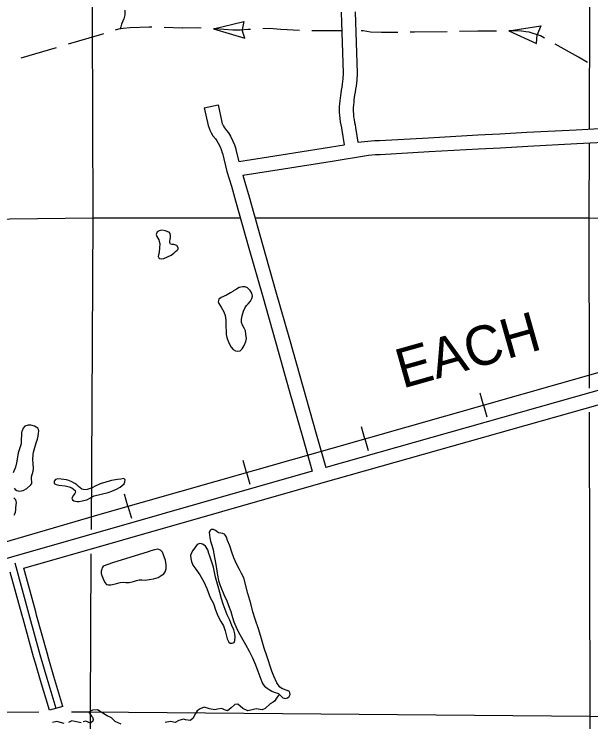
# Model space of a CAD drawing. Extents: x 1373094 to 1376427, y 1168361 to 1170494.
# Drawn here: x 1373576.1 to 1373679.1, y 1169997.1 to 1170123.5 of the extents above; entities that cross this region are included whole.
import ezdxf

# ---------------------------------------------------------------- set-up
doc = ezdxf.new("R2010")
doc.units = 0
doc.layers.add('R_Axis', color=7, linetype='Continuous')

msp = doc.modelspace()

# ---------------------------------------------------------------- linework, layer by layer
at = {"layer": 'R_Axis'}
for p, q in [((1373611.69, 1170120.9), (1373617.1, 1170122.17)), ((1373617.1, 1170122.17), (1373616.8, 1170120.68)), ((1373611.69, 1170120.9), (1373617.3, 1170119.22)), ((1373664.42, 1170120.5), (1373670.14, 1170121.4)), ((1373670.14, 1170121.4), (1373669.47, 1170119.82)), ((1373617.3, 1170119.22), (1373616.8, 1170120.66)), ((1373664.42, 1170120.5), (1373669.39, 1170118.28)), ((1373669.39, 1170118.28), (1373669.47, 1170119.8)), ((1373610.04, 1170106.78), (1373612.49, 1170107.32)), ((1373659.89, 1170053.66), (1373659.29, 1170055.78)), ((1373659.89, 1170053.66), (1373660.49, 1170051.54)), ((1373638.73, 1170047.64), (1373638.13, 1170049.76)), ((1373638.73, 1170047.64), (1373639.33, 1170045.53)), ((1373617.57, 1170041.63), (1373616.97, 1170043.74)), ((1373617.57, 1170041.63), (1373618.17, 1170039.51)), ((1373596.41, 1170035.61), (1373595.81, 1170037.72)), ((1373596.41, 1170035.61), (1373597.01, 1170033.49)), ((1373584.77, 1169999.84), (1373582.37, 1169999.14))]:
    msp.add_line(p, q, dxfattribs=at)
for points in [[(1373590.16, 1170175.98), (1373590.03, 1170122.63)], [(1373678.85, 1170124.81), (1373678.77, 1170102.99)], [(1373595.83, 1170124.22), (1373595.86, 1170123.4), (1373595.68, 1170122.68), (1373595.44, 1170122.13), (1373595.25, 1170121.69), (1373595.13, 1170121.25), (1373594.99, 1170120.85)], [(1373634.48, 1170123.86), (1373634.82, 1170112.94), (1373634.79, 1170111.92), (1373634.67, 1170110.98), (1373634.59, 1170110.46), (1373634.5, 1170109.94), (1373634.42, 1170109.4), (1373634.34, 1170108.94), (1373634.29, 1170108.47), (1373634.23, 1170108.02), (1373634.19, 1170107.5), (1373634.14, 1170106.99), (1373634.12, 1170106.61), (1373634.11, 1170106.01), (1373634.18, 1170105.4), (1373634.22, 1170104.84), (1373634.33, 1170104.25), (1373634.41, 1170103.71), (1373634.52, 1170103.21), (1373634.61, 1170102.78), (1373635, 1170100.13)], [(1373636.98, 1170123.92), (1373637.32, 1170112.94), (1373637.29, 1170111.72), (1373637.14, 1170110.62), (1373637.05, 1170110.07), (1373636.97, 1170109.55), (1373636.89, 1170109.01), (1373636.82, 1170108.6), (1373636.77, 1170108.17), (1373636.72, 1170107.78), (1373636.69, 1170107.29), (1373636.63, 1170106.77), (1373636.62, 1170106.51), (1373636.61, 1170106.15), (1373636.68, 1170105.62), (1373636.71, 1170105.15), (1373636.79, 1170104.67), (1373636.87, 1170104.15), (1373636.96, 1170103.72), (1373637.07, 1170103.22), (1373637.46, 1170100.62)], [(1373590.03, 1170122.63), (1373590.11, 1170087.11), (1373589.81, 1170031.44)], [(1373600.69, 1170121.16), (1373600.18, 1170121.17), (1373596.77, 1170121.08), (1373595.54, 1170120.95), (1373594.72, 1170120.81), (1373594.14, 1170120.63)], [(1373606.19, 1170121), (1373606.12, 1170121), (1373602.89, 1170121.09)], [(1373609.49, 1170121.01), (1373608.98, 1170121.04), (1373606.19, 1170121)], [(1373618.27, 1170120.77), (1373617.81, 1170120.74), (1373616.46, 1170120.65), (1373615.13, 1170120.61), (1373613.53, 1170120.74), (1373611.9, 1170120.86), (1373611.68, 1170120.87)], [(1373627.05, 1170120.55), (1373627.03, 1170120.55), (1373623.73, 1170120.75), (1373621.64, 1170120.94), (1373620.47, 1170120.89)], [(1373592.04, 1170119.96), (1373591.26, 1170119.73), (1373585.71, 1170118.11)], [(1373634.58, 1170120.5), (1373629.25, 1170120.54)], [(1373644.62, 1170120.24), (1373641.69, 1170120.19), (1373639.73, 1170120.28), (1373638.44, 1170120.51), (1373638.05, 1170120.53)], [(1373653.42, 1170120.36), (1373647.58, 1170120.29), (1373646.82, 1170120.28)], [(1373658.92, 1170120.43), (1373655.62, 1170120.39)], [(1373662.22, 1170120.47), (1373658.92, 1170120.43)], [(1373670.8, 1170119.22), (1373670.09, 1170119.62), (1373668.04, 1170120.27), (1373667.47, 1170120.32), (1373666.67, 1170120.45), (1373665.3, 1170120.51), (1373664.42, 1170120.5)], [(1373583.6, 1170117.5), (1373577.26, 1170115.65)], [(1373678.46, 1170114.87), (1373676.87, 1170115.82), (1373672.72, 1170118.14)], [(1373612.49, 1170107.32), (1373613.17, 1170104.22), (1373613.25, 1170103.93), (1373613.29, 1170103.83), (1373613.46, 1170103.5), (1373613.65, 1170103.2), (1373614.01, 1170102.71), (1373614.34, 1170102.28), (1373614.71, 1170101.69), (1373615.15, 1170100.83), (1373615.42, 1170100.14), (1373615.65, 1170099.42), (1373615.69, 1170099.28)], [(1373610.04, 1170106.78), (1373610.74, 1170103.61), (1373610.89, 1170103.11), (1373611.02, 1170102.78), (1373611.28, 1170102.27), (1373611.58, 1170101.79), (1373612.01, 1170101.21), (1373612.28, 1170100.86), (1373612.54, 1170100.45), (1373612.87, 1170099.81), (1373613.06, 1170099.31), (1373613.25, 1170098.74), (1373613.26, 1170098.67)], [(1373676.46, 1170102.86), (1373684.91, 1170103.32), (1373685.32, 1170103.32)], [(1373650.09, 1170101.43), (1373658.88, 1170101.91)], [(1373658.88, 1170101.91), (1373662.81, 1170102.13), (1373667.67, 1170102.39)], [(1373667.67, 1170102.39), (1373676.46, 1170102.86)], [(1373637.46, 1170100.62), (1373640.45, 1170100.9), (1373641.31, 1170100.95)], [(1373641.31, 1170100.95), (1373650.09, 1170101.43)], [(1373676.59, 1170100.37), (1373684.96, 1170100.82), (1373685.3, 1170100.82)], [(1373623.78, 1170098.35), (1373635, 1170100.13)], [(1373650.23, 1170098.94), (1373659.02, 1170099.42)], [(1373659.02, 1170099.42), (1373662.95, 1170099.63), (1373667.8, 1170099.9)], [(1373667.8, 1170099.9), (1373676.59, 1170100.37)], [(1373678.76, 1170100.49), (1373678.71, 1170087.1), (1373678.77, 1170056.7)], [(1373613.26, 1170098.67), (1373614.08, 1170095.4), (1373614.87, 1170092.78), (1373615.62, 1170090.15)], [(1373615.69, 1170099.28), (1373616.22, 1170097.15)], [(1373616.22, 1170097.15), (1373623.78, 1170098.35)], [(1373632.86, 1170097.26), (1373639.39, 1170098.29), (1373640.64, 1170098.41), (1373641.44, 1170098.45)], [(1373641.44, 1170098.45), (1373650.23, 1170098.94)], [(1373624.17, 1170095.88), (1373632.86, 1170097.26)], [(1373616.9, 1170094.72), (1373624.17, 1170095.88)], [(1373616.9, 1170094.72), (1373617.27, 1170093.49), (1373618.03, 1170090.84)], [(1373618.03, 1170090.84), (1373620.43, 1170082.37)], [(1373615.62, 1170090.15), (1373618.02, 1170081.69)], [(1373535.69, 1170086.46), (1373590.11, 1170087.11), (1373616.48, 1170087.11)], [(1373619.08, 1170087.11), (1373678.71, 1170087.1), (1373747.2, 1170084.66)], [(1373603.93, 1170084.29), (1373603.74, 1170084.53), (1373603.52, 1170084.63), (1373603.1, 1170084.8), (1373602.48, 1170084.89), (1373601.99, 1170084.78), (1373601.63, 1170084.6), (1373601.46, 1170084.16), (1373601.58, 1170083.78), (1373601.89, 1170083.16), (1373602.11, 1170082.43), (1373602.06, 1170081.83), (1373601.95, 1170080.94), (1373601.88, 1170080.49), (1373601.82, 1170080.23), (1373601.9, 1170079.95), (1373602.03, 1170079.86), (1373602.32, 1170079.76), (1373602.8, 1170079.86), (1373603.46, 1170080.12), (1373604.11, 1170080.47), (1373604.58, 1170080.8), (1373604.92, 1170081.08), (1373605.17, 1170081.32), (1373605.36, 1170081.53), (1373605.39, 1170081.76), (1373605.16, 1170082.19), (1373604.59, 1170082.32), (1373604.21, 1170082.33), (1373604.02, 1170082.39), (1373603.92, 1170082.5), (1373603.88, 1170082.7), (1373603.9, 1170082.97), (1373603.96, 1170083.3), (1373604, 1170083.57), (1373603.99, 1170083.91), (1373603.93, 1170084.29)], [(1373618.02, 1170081.69), (1373620.42, 1170073.22)], [(1373620.43, 1170082.37), (1373622.83, 1170073.9)], [(1373546.2, 1170020.93), (1373591.87, 1170034.32), (1373741.71, 1170076.93)], [(1373546.2, 1170020.93), (1373591.87, 1170034.32), (1373741.71, 1170076.93)], [(1373755.25, 1170077.44), (1373631.72, 1170042.54)], [(1373577.78, 1170024.53), (1373630.86, 1170039.7), (1373756.46, 1170075.18)], [(1373615.27, 1170074.05), (1373615.15, 1170073.96), (1373614.73, 1170073.73), (1373614.01, 1170073.32), (1373613.06, 1170072.88), (1373612.61, 1170072.6), (1373612.53, 1170072.13), (1373612.61, 1170071.78), (1373613.07, 1170071.14), (1373613.55, 1170070.32), (1373613.78, 1170069.66), (1373613.91, 1170068.81), (1373613.89, 1170067.71), (1373613.92, 1170066.84), (1373613.95, 1170066.28), (1373614.07, 1170065.74), (1373614.34, 1170064.89), (1373614.82, 1170064), (1373615.21, 1170063.59), (1373615.59, 1170063.37), (1373616.02, 1170063.28), (1373616.43, 1170063.36), (1373616.81, 1170063.71), (1373617.17, 1170064.3), (1373617.47, 1170065), (1373617.58, 1170065.57), (1373617.48, 1170066.33), (1373617.38, 1170066.93), (1373617.15, 1170067.41), (1373616.86, 1170067.93), (1373616.67, 1170068.43), (1373616.68, 1170069.01), (1373616.81, 1170069.6), (1373617.04, 1170070.44), (1373617.32, 1170071.09), (1373617.56, 1170071.44), (1373617.85, 1170071.77), (1373618.28, 1170072.22), (1373618.53, 1170072.69), (1373618.62, 1170073.13), (1373618.52, 1170073.66), (1373618.22, 1170074.15), (1373617.76, 1170074.61), (1373617.36, 1170074.78), (1373616.84, 1170074.81), (1373616.26, 1170074.68), (1373615.77, 1170074.39), (1373615.27, 1170074.05)], [(1373620.42, 1170073.22), (1373622.82, 1170064.76)], [(1373622.83, 1170073.9), (1373625.23, 1170065.44)], [(1373625.23, 1170065.44), (1373627.63, 1170056.97)], [(1373622.82, 1170064.76), (1373625.22, 1170056.29)], [(1373627.63, 1170056.97), (1373630.03, 1170048.5)], [(1373625.22, 1170056.29), (1373627.62, 1170047.82)], [(1373678.78, 1170052.37), (1373678.87, 1169998.09), (1373678.78, 1169973.84)], [(1373580.32, 1170049.55), (1373579.71, 1170049.89), (1373579.06, 1170050.06), (1373578.59, 1170050.09), (1373578, 1170049.91), (1373577.71, 1170049.53), (1373577.49, 1170049.06), (1373577.38, 1170048.84), (1373577.37, 1170048.24), (1373577.34, 1170047.55), (1373577.31, 1170046.75), (1373577.12, 1170046.04), (1373576.78, 1170045.15), (1373576.65, 1170044.38), (1373576.51, 1170043.37), (1373576.29, 1170042.59), (1373575.89, 1170041.56)], [(1373576.05, 1170038.83), (1373576.26, 1170038.59), (1373576.58, 1170038.4), (1373577, 1170038.31), (1373577.71, 1170038.41), (1373578.37, 1170038.77), (1373579.03, 1170039.39), (1373579.21, 1170039.63), (1373579.25, 1170039.91), (1373579.2, 1170040.46), (1373579.17, 1170040.86), (1373579.5, 1170041.86), (1373579.56, 1170042.38), (1373579.48, 1170043.16), (1373579.39, 1170043.94), (1373579.45, 1170044.86), (1373579.52, 1170045.28), (1373579.76, 1170046.07), (1373580, 1170046.91), (1373580.23, 1170047.59), (1373580.36, 1170048.13), (1373580.45, 1170048.63), (1373580.47, 1170049.02), (1373580.43, 1170049.32), (1373580.32, 1170049.55)], [(1373627.62, 1170047.82), (1373629.31, 1170041.86)], [(1373630.03, 1170048.5), (1373631.72, 1170042.54)], [(1373629.31, 1170041.86), (1373575.61, 1170026.51), (1373565.85, 1170023.68), (1373541.62, 1170016.56), (1373541.3, 1170016.47), (1373540.91, 1170016.42), (1373539.97, 1170016.35), (1373539.13, 1170016.33), (1373538.49, 1170016.35), (1373537.88, 1170016.38), (1373537.25, 1170016.43), (1373536.59, 1170016.5)], [(1373586.52, 1170036.72), (1373586.72, 1170036.58), (1373587.01, 1170036.49), (1373587.31, 1170036.45), (1373587.67, 1170036.46), (1373588.25, 1170036.56), (1373589.03, 1170036.75), (1373589.7, 1170037.09), (1373590.35, 1170037.43), (1373592.85, 1170038.06), (1373593.54, 1170038.28), (1373594.34, 1170038.65), (1373595.01, 1170039.02), (1373595.37, 1170039.27), (1373595.71, 1170039.59), (1373595.85, 1170039.98), (1373595.92, 1170040.29), (1373595.67, 1170040.53), (1373595.14, 1170040.45), (1373594.54, 1170040.38), (1373593.46, 1170040.19), (1373591.45, 1170039.62), (1373590.45, 1170039.14), (1373589.99, 1170038.9), (1373589.14, 1170038.56), (1373588.62, 1170038.51), (1373588.19, 1170038.62), (1373587.88, 1170038.86), (1373587.56, 1170039.13), (1373587.25, 1170039.41), (1373586.93, 1170039.63), (1373586.37, 1170039.95), (1373585.86, 1170040.2), (1373585.41, 1170040.3), (1373584.46, 1170040.44), (1373583.86, 1170040.49), (1373583.45, 1170040.38), (1373583.24, 1170040.09), (1373583.23, 1170039.68), (1373583.57, 1170039.48), (1373584.03, 1170039.34), (1373585.18, 1170039.24), (1373585.88, 1170039.08), (1373586.37, 1170038.88), (1373586.95, 1170038.43), (1373587, 1170038.35), (1373587.04, 1170038.13), (1373586.93, 1170037.88), (1373586.66, 1170037.6), (1373586.39, 1170037.06), (1373586.52, 1170036.72)], [(1373576.45, 1170036.48), (1373576.33, 1170036.77), (1373576.04, 1170037.11)], [(1373576.05, 1170033.99), (1373576.22, 1170034.25), (1373576.3, 1170034.53), (1373576.37, 1170034.97), (1373576.39, 1170035.39), (1373576.48, 1170036.29), (1373576.45, 1170036.48)], [(1373611.29, 1170031.42), (1373611.06, 1170031.26), (1373610.92, 1170030.97), (1373610.94, 1170030.44), (1373611, 1170029.94), (1373611.17, 1170029.34), (1373611.39, 1170028.62), (1373611.6, 1170027.8), (1373611.72, 1170027.12), (1373612.03, 1170025.5), (1373612.15, 1170024.83), (1373612.27, 1170024.05), (1373612.4, 1170023.27), (1373612.59, 1170022.34), (1373612.9, 1170021.42), (1373613.64, 1170019.55), (1373613.98, 1170018.88), (1373614.39, 1170017.84), (1373614.76, 1170016.78), (1373615.09, 1170015.74), (1373615.31, 1170014.94), (1373615.68, 1170014.12), (1373616.16, 1170013.12), (1373617.38, 1170010.92), (1373618.08, 1170009.69), (1373618.66, 1170008.5), (1373619.2, 1170007.25), (1373619.62, 1170006.14), (1373620.3, 1170004.24), (1373620.39, 1170004.05), (1373620.54, 1170003.77), (1373620.81, 1170003.47), (1373621.24, 1170003.12), (1373621.61, 1170002.83), (1373622.13, 1170002.58), (1373622.51, 1170002.39), (1373623.31, 1170002.16), (1373623.79, 1170001.69), (1373624.07, 1170001.39), (1373624.3, 1170001.28), (1373624.5, 1170001.26), (1373624.88, 1170001.38), (1373625.21, 1170001.59), (1373625.36, 1170001.98), (1373625.34, 1170002.26), (1373625.28, 1170002.49), (1373624.84, 1170002.69), (1373624, 1170003), (1373623.53, 1170003.29), (1373623, 1170004.06), (1373622.44, 1170005.24), (1373622.13, 1170006.13), (1373621.21, 1170008.88), (1373620.76, 1170010.25), (1373620.27, 1170011.91), (1373619.76, 1170013.54), (1373619.15, 1170015.44), (1373618.73, 1170016.75), (1373618.34, 1170018.19), (1373617.82, 1170020.03), (1373617.07, 1170022.78), (1373616.71, 1170023.6), (1373616.33, 1170024.31), (1373615.8, 1170025.31), (1373615.33, 1170026.35), (1373614.95, 1170027.37), (1373614.57, 1170028.5), (1373614.21, 1170029.47), (1373614.01, 1170030.05), (1373613.82, 1170030.34), (1373613.64, 1170030.59), (1373613.34, 1170030.75), (1373612.99, 1170030.78), (1373612.6, 1170030.86), (1373612.26, 1170031.08), (1373612.01, 1170031.26), (1373611.67, 1170031.45), (1373611.29, 1170031.42)], [(1373609.74, 1170028.84), (1373609.22, 1170028.92), (1373608.74, 1170028.74), (1373608.47, 1170028.36), (1373607.99, 1170027.71), (1373607.74, 1170027.27), (1373607.6, 1170026.78), (1373607.62, 1170026.28), (1373607.75, 1170025.73), (1373608, 1170025.07), (1373608.54, 1170024.36), (1373609.22, 1170023.31), (1373609.94, 1170022.06), (1373610.47, 1170020.87), (1373611.09, 1170019.31), (1373611.67, 1170018.19), (1373612.05, 1170017.08), (1373612.48, 1170015.99), (1373613.01, 1170015.01), (1373613.47, 1170014.2), (1373613.78, 1170013.31), (1373614.15, 1170011.9), (1373614.4, 1170011.31), (1373614.66, 1170011.13), (1373615.03, 1170011.11), (1373615.35, 1170011.27), (1373615.51, 1170011.59), (1373615.57, 1170012.26), (1373615.47, 1170012.8), (1373615.3, 1170013.51), (1373614.98, 1170014.28), (1373614.57, 1170015.27), (1373614.12, 1170016.21), (1373613.78, 1170017.17), (1373613.43, 1170018.09), (1373613.11, 1170019.08), (1373612.79, 1170020.19), (1373612.49, 1170021.27), (1373612.28, 1170022.06), (1373612.03, 1170022.91), (1373611.69, 1170024.72), (1373611.2, 1170026.11), (1373611.01, 1170026.68), (1373610.85, 1170027.16), (1373610.67, 1170027.81), (1373610.23, 1170028.45), (1373610.04, 1170028.61), (1373609.74, 1170028.84)], [(1373600.03, 1170027.46), (1373593.62, 1170025.47), (1373591.99, 1170024.9), (1373591.78, 1170024.59), (1373591.72, 1170024.36), (1373591.62, 1170023.99), (1373591.6, 1170023.59), (1373591.71, 1170023.21), (1373591.97, 1170022.61), (1373592.29, 1170021.99), (1373592.57, 1170021.63), (1373592.84, 1170021.54), (1373593.37, 1170021.55), (1373594.18, 1170021.73), (1373595.02, 1170021.95), (1373595.52, 1170022.05), (1373596.05, 1170021.99), (1373596.62, 1170021.95), (1373597.38, 1170022.13), (1373597.92, 1170022.34), (1373598.42, 1170022.46), (1373598.87, 1170022.45), (1373599.5, 1170022.41), (1373600.19, 1170022.53), (1373600.96, 1170022.65), (1373601.81, 1170022.89), (1373602.32, 1170023.21), (1373602.83, 1170023.53), (1373603.06, 1170023.9), (1373603.25, 1170024.42), (1373603.24, 1170025.11), (1373603.09, 1170025.94), (1373602.94, 1170026.4), (1373602.76, 1170026.9), (1373602.56, 1170027.39), (1373602.23, 1170027.72), (1373601.76, 1170027.93), (1373601.17, 1170027.82), (1373600.46, 1170027.63), (1373600.03, 1170027.46)], [(1373589.79, 1170027.1), (1373589.64, 1169998.89), (1373589.49, 1169953.62)], [(1373583.57, 1169999.49), (1373582, 1170004.84), (1373580.75, 1170009.05), (1373578.89, 1170015.79), (1373576.25, 1170025.4)], [(1373577.51, 1170016.08), (1373575.38, 1170023.84)], [(1373579.93, 1170016.74), (1373577.78, 1170024.53)], [(1373579.89, 1170007.58), (1373579.55, 1170008.71), (1373577.68, 1170015.46), (1373577.51, 1170016.08)], [(1373582.28, 1170008.28), (1373581.96, 1170009.4), (1373580.09, 1170016.13), (1373579.93, 1170016.74)], [(1373582.37, 1169999.14), (1373580.8, 1170004.48), (1373579.89, 1170007.58)], [(1373584.77, 1169999.84), (1373583.19, 1170005.19), (1373582.28, 1170008.28)], [(1373623.46, 1170002.01), (1373623.18, 1170001.69), (1373622.59, 1170000.79), (1373622.31, 1170000.58), (1373621.8, 1170000.31), (1373620.88, 1169999.47), (1373620.37, 1169999.25), (1373619.32, 1169999.42), (1373618.61, 1169999.23), (1373617.83, 1169999.03), (1373616.9, 1169999.48), (1373616.05, 1170000.24), (1373615.52, 1170000.19), (1373614.82, 1169999.6), (1373614.17, 1169999.07), (1373613.67, 1169999.22), (1373613.16, 1169999.49), (1373612.38, 1169999.33), (1373611.91, 1169999.2), (1373610.95, 1169999.42), (1373610.04, 1169999.69), (1373609.29, 1169999.42), (1373608.77, 1169999.02), (1373608.46, 1169998.57), (1373607.98, 1169997.66), (1373607.49, 1169997.33), (1373606.69, 1169997.42), (1373606.33, 1169997.56), (1373605.46, 1169997.32), (1373604.82, 1169996.95), (1373604.02, 1169997.12), (1373603.04, 1169996.94)], [(1373507.32, 1169998.51), (1373580.46, 1169998.85)], [(1373586.29, 1169998.87), (1373589.64, 1169998.89), (1373678.87, 1169998.09), (1373716.62, 1169997.13)], [(1373595.18, 1169996.64), (1373594.1, 1169997.14), (1373593.47, 1169997.82), (1373592.67, 1169998.18), (1373591.62, 1169998.8), (1373590.98, 1169999.25), (1373590.07, 1169999.19), (1373589.43, 1169998.8), (1373589.9, 1169998.11), (1373590.04, 1169997.93), (1373590.18, 1169997.5), (1373590.13, 1169997.18), (1373589.74, 1169996.82), (1373588.9, 1169997.2), (1373588.38, 1169997.06)], [(1373584.98, 1169996.81), (1373583.67, 1169997.16), (1373582.91, 1169996.95)], [(1373588.07, 1169996.89), (1373586.93, 1169997.14), (1373586.4, 1169997.26), (1373585.78, 1169996.94)]]:
    msp.add_lwpolyline(points, dxfattribs=at)

# ---------------------------------------------------------------- texts
msp.add_text('EACH', height=7.04, rotation=15.7751, dxfattribs=at).set_placement((1373645.44, 1170056.59))

doc.saveas('drawing.dxf')
